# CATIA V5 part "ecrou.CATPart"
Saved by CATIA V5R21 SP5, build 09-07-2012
Part number: ecrou
Bounding box of the stored display mesh (mm): x -115.47 to 115.47, y -100 to 100, z 0 to 200
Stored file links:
  \\etu.ad.univ-lorraine.fr\bordron1\Documents\Parts EPR\ecrou.CATPart
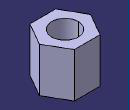
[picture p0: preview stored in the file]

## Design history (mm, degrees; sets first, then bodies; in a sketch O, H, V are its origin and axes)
AxisSystem1: origin (0, 0, 0), X (1, 0, 0), Y (0, 1, 0), Z (0, 0, 1)
Body1 (main body)
  Sketch1 on XY plane of AxisSystem1, origin (0, 0, 0), H (1, 0, 0), V (0, 1, 0)
    circle A1 centre (0, 0) radius 60
    point P1 (57.735, -100)
    point P2 (115.4701, 0)
    point P3 (57.735, 100)
    point P4 (-57.735, 100)
    point P5 (-115.4701, 0)
    point P6 (-57.735, -100)
    point P7 (86.6025, -50)
    line L1 (57.735, -100) -> (115.4701, 0)
    line L2 (115.4701, 0) -> (57.735, 100)
    line L3 (57.735, 100) -> (-57.735, 100)
    line L4 (-57.735, 100) -> (-115.4701, 0)
    line L5 (-115.4701, 0) -> (-57.735, -100)
    line L6 (-57.735, -100) -> (57.735, -100)
    construction line L7 (0, 0) -> (86.6025, -50)
    construction circle A2 centre (0, 0) radius 115.4701
    construction arc A3 centre (-115.4701, 0) radius 115.4701 from (-57.735, 100) to (-57.735, -100) cw
    construction arc A4 centre (115.4701, 0) radius 115.4701 from (57.735, 100) to (57.735, -100) ccw
    radius A1 = 60
    distance L1 L4 = 200
    coincidence: A2 P1, A2 P2, A2 P3, A2 P4, A2 P5, A2 P6, A3 O, A4 O
    midpoint: P7 L1
    horizontal: L3 H
  Pad1: profile Sketch1, direction (0, 0, 1), length 200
